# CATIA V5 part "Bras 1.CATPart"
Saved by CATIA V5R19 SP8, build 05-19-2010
Part number: Bras 1
Bounding box of the stored display mesh (mm): x -756 to 604, y -30 to 115.652, z -30 to 335.41
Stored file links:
  G:\EU_thinkMotion\CFAO_2010\MMS_groupe1\MMS_groupe1\OK\rragonneau\rragonneau\Bras 1.CATPart
  D:\Documents\Scolaire\MM2\CFAO\Brevet\MODELE CATIA\Squelette\Deambulateur.CATProduct
  G:\EU_thinkMotion\CFAO_2010\MMS_groupe1\MMS_groupe1\OK\rragonneau\rragonneau\squelette bras 1.CATPart
  G:\EU_thinkMotion\CFAO_2010\MMS_groupe1\MMS_groupe1\OK\rragonneau\rragonneau\squelette de base.CATPart
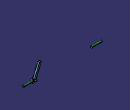
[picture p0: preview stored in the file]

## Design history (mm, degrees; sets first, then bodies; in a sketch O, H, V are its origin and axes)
External parameters (linked from other documents)
  `External.diam_moyeu_ext / epaisseur_bras&montant` = 60 mm
  External.diam_axe = 30 mm
  External.epaisseur_pneu = 60 mm
Set1
  Sketch1 on Plane1, origin (424, 0, 0), H (0, 1, 0), V (0, 0, 1)
    circle A1 centre (0, 0) radius 30
    radius A1 = 30 {= `External.diam_moyeu_ext / epaisseur_bras&montant` /2}
  Sketch2 on Plane1, origin (424, 0, 0), H (0, 1, 0), V (0, 0, 1)
    line L1 (84.3475, 335.4102) -> (115.6525, 335.4102)
    line L2 (115.6525, 335.4102) -> (17.8885, 7.5)
    line L3 (17.8885, 7.5) -> (-13.4164, 7.5)
    line L4 (-13.4164, 7.5) -> (84.3475, 335.4102)
    reference intersected line E1 through (0, 335.4102) direction (-1, 0) from Plane2
    reference projected line E2 (142.8571, 479.1574) -> (0, 0) from Line1
    reference projected line E3 (142.8571, 479.1574) -> (0, 0) from Line1
    reference projected line E4 (142.8571, 479.1574) -> (0, 0) from Line1
    reference projected line E5 (142.8571, 479.1574) -> (0, 0) from Line1
    distance L3 H = 7.5 {= `External.diam_moyeu_ext / epaisseur_bras&montant` /8}
    distance E4 L2 = 15 {= `External.diam_moyeu_ext / epaisseur_bras&montant` /4}
    distance L4 E5 = 15 {= `External.diam_moyeu_ext / epaisseur_bras&montant` /4}
    horizontal: L1 H, L3 H
    coincidence: L1 E1
    parallelism: L2 E2, L4 E3
Set2
  Plane1: linked copy from another document
  Plane2: linked copy from another document
  Line1: linked copy from another document
  Plane3: linked copy from another document
Body1 (main body)
  Pad1: profile Sketch1, direction (1, 0, 0), length 22 {= `External.diam_moyeu_ext / epaisseur_bras&montant` /4+7mm}, opposite side length 22 {= `External.diam_moyeu_ext / epaisseur_bras&montant` /4+7mm}
  Pad2: profile Sketch2, direction (1, 0, 0), length 15 {= `External.diam_moyeu_ext / epaisseur_bras&montant`/4}, opposite side length 15 {= `External.diam_moyeu_ext / epaisseur_bras&montant` /4}
  Sketch3 on Plane1, origin (424, 0, 0), H (0, 1, 0), V (0, 0, 1)
    circle A1 centre (0, 0) radius 15
    radius A1 = 15 {= External.diam_axe /2}
  Pad3: profile Sketch3, direction (1, 0, 0), length 180 {= External.epaisseur_pneu *3}
  Mirror1: of Pad3, about Plane3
